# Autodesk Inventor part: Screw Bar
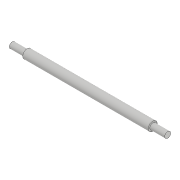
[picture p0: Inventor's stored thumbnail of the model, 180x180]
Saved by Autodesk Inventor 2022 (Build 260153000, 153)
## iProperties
Created: 2016-03
Part Number: Screw Bar
Material: Generic
Document SubType Name: Modeling
Designer: Sandeep
Density: 1 g/cm^3
Appearance: Default
Mass: 2.62637 g
Surface Area: 18.9124 cm^2
Volume: 2.62637 cm^3
Author: Sandeep
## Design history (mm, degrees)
sketch "Sketch1"
  geometry: L1 (-104, 2)-(-94, 2); L2 (-94, 2)-(-94, 3); L3 (-94, 3)-(-10, 3); L4 (-10, 3)-(-10, 2); L5 (-10, 2)-(0, 2); L6 (0, 2)-(0, 0); L7 (-104, 2)-(-104, 0); L8 (-104, 0)-(0, 0); L9 (0, 0)-(21.698, 0)
  constraints: 18 end point, 4 perpendicular, 3 horizontal, 2 point on line, 1 vertical
  dimensions: "d0" = 4 diameter of L5 L9; "d1" = 6 diameter of L3 L9; "d2" = 10 distance of L4.end L5.end; "d3" = 10 distance of L1.start L1.end; "d4" = 104 distance between parallel lines of L7 L6
revolve "Revolution1" sketch "Sketch1" stored, may be unused: angle "d5" = 90 deg
body "Solid1"
